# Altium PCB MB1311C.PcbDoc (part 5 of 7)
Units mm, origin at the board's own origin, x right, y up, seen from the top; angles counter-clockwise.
Board outline 100.03 x 67.03 mm, 6 copper layers (Top Layer, layer2, layer3, layer4, layer5, Bottom Layer), stack 1.208 mm thick; 366 components, 356 nets, 1582 pads, 964 vias.
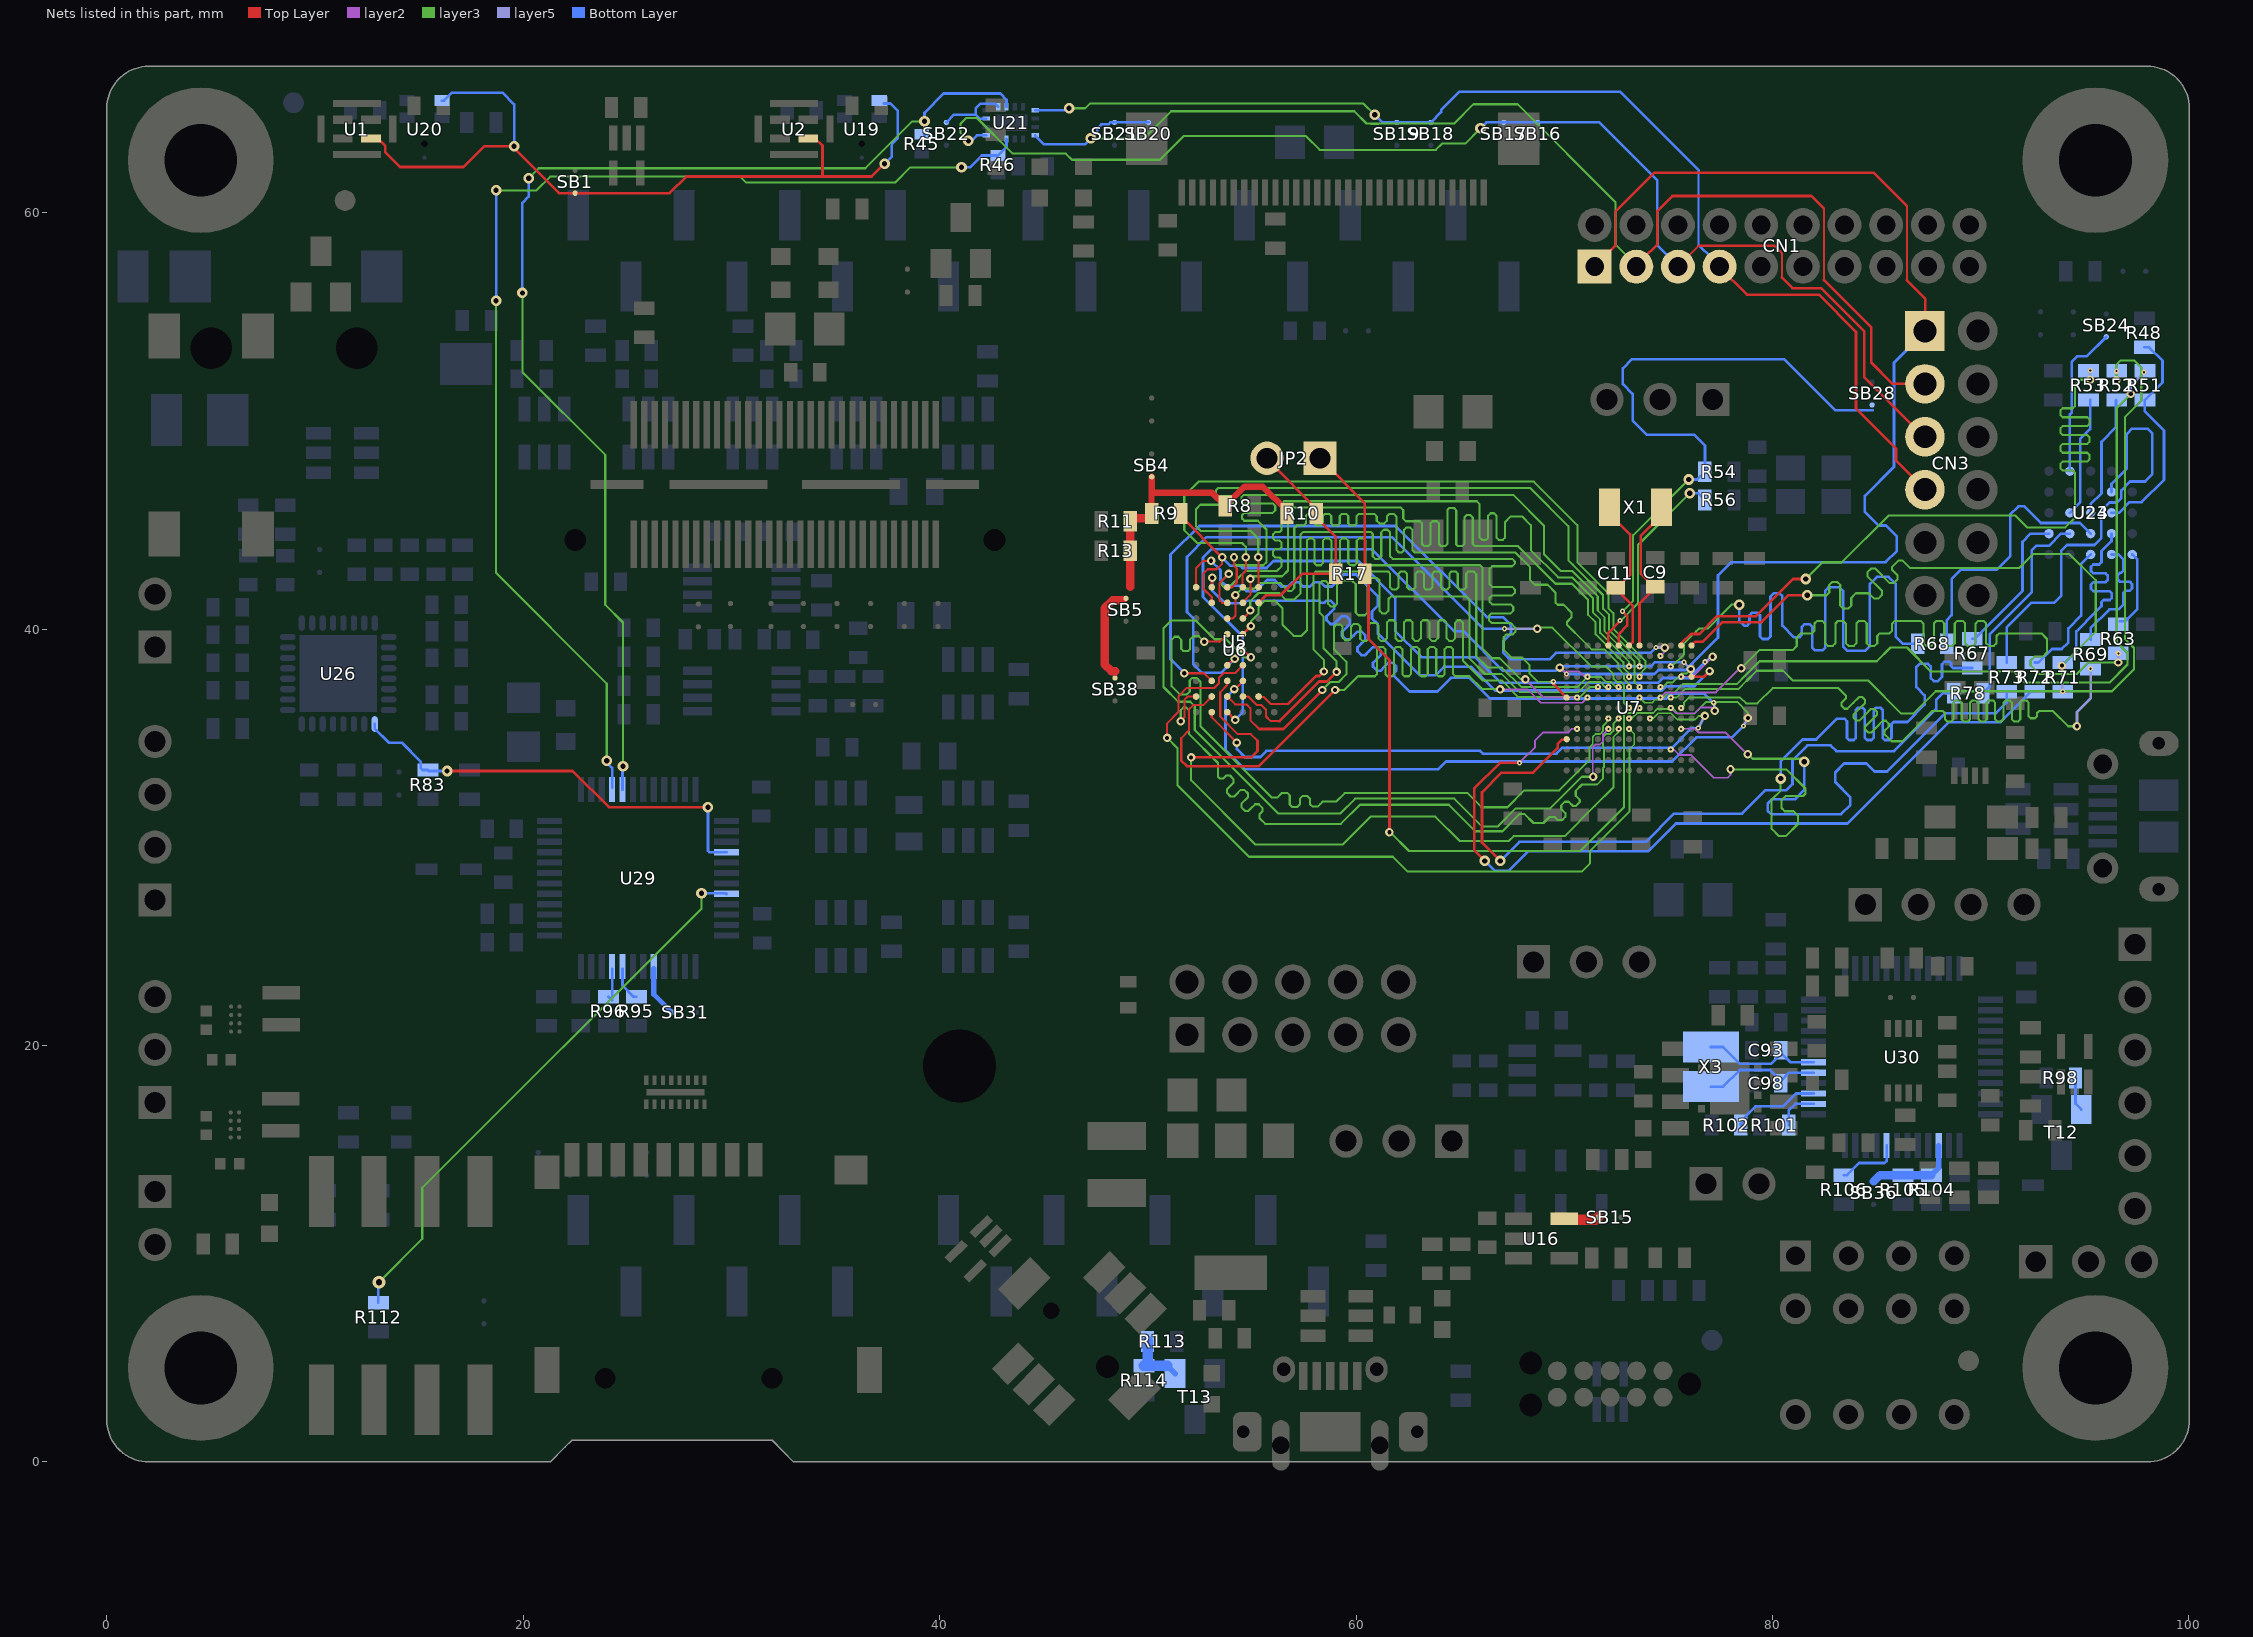
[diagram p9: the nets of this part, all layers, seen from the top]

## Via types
v1: diameter 0.508, hole 0.254, Top Layer to Bottom Layer, tented both sides, 462 vias
v2: diameter 0.61, hole 0.305, Top Layer to Bottom Layer, tented both sides, 126 vias
v3: diameter 0.406, hole 0.203, layer2 to layer5, tented both sides, 109 vias
v4: diameter 0.25, hole 0.1, Top Layer to layer2, tented both sides, 80 vias
v5: diameter 0.25, hole 0.1, Top Layer to layer3, tented both sides, 78 vias
v6: diameter 0.25, hole 0.1, layer5 to Bottom Layer, tented both sides, 52 vias
v7: diameter 0.406, hole 0.203, Top Layer to Bottom Layer, tented both sides, 48 vias
v8: diameter 0.508, hole 0.254, layer2 to layer5, tented both sides, 4 vias
v9: diameter 0.406, hole 0.203, layer2 to layer5, 3 vias
v10: diameter 0.25, hole 0.1, layer5 to Bottom Layer, tented bottom, 1 vias
v11: diameter 0.25, hole 0.1, Top Layer to layer3, tented top, 1 vias

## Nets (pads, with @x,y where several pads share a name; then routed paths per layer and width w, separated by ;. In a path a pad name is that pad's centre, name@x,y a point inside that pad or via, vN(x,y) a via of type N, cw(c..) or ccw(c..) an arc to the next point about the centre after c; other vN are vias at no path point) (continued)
NetR83_2: R83.2 U26.25 U29.28 | length 21
  Top Layer w0.127: v1(16.343,33.183) 22.371,33.183 24.111,31.443 v1(28.873,31.443)
  Bottom Layer w0.127: U26.25@12.863,35.443 12.863,35.233 13.558,34.538 14.168,34.538 15.073,33.633 15.073,33.323 15.167,33.229 R83.2@15.423,33.229 15.469,33.183 v1(16.343,33.183) ; v1(28.873,31.443) 28.873,29.359 28.949,29.283 U29.28@29.771,29.283
NetR95_1: R95.1 U29.44 | length 1.7
  Bottom Layer w0.127: U29.44@24.771,23.683 24.771,22.875 25.307,22.339 R95.1@25.438,22.339
NetR96_1: R96.1 U29.45 | length 1.8
  Bottom Layer w0.127: R96.1@24.096,22.339 24.271,22.164 U29.45@24.271,23.683
NetR98_1: R98.1 T12.2 | length 1.6
  Bottom Layer w0.127: R98.1@94.553,18.443 94.553,17.203 T12.2@94.833,16.923
NetR101_2: R101.2 U30.2 | length 2
  Bottom Layer w0.127: R101.2@80.783,16.173 80.783,16.866 81.11,17.193 U30.2@81.983,17.193
NetR102_2: R102.2 U30.3 | length 4.3
  Bottom Layer w0.127: R102.2@78.463,16.213 R102.2@78.483,16.233 ; R102.2@78.483,16.173 R102.2@78.483,16.233 ; U30.3@81.983,17.693 81.133,17.693 80.526,17.086 79.207,17.086 78.702,16.581 78.702,16.452 R102.2@78.483,16.233
NetR104_1: R104.1 R105.2 SB36.2 U30.39 | length 4.5
  Bottom Layer w0.254: R104.1@87.643,13.773 87.983,14.113 U30.39@87.983,15.193
  Bottom Layer w0.4: SB36.2@84.863,13.463 85.173,13.773 R105.2@86.273,13.773 R104.1@87.643,13.773
NetR106_1: R106.1 U30.44 | length 3.1
  Bottom Layer w0.127: R106.1@83.423,13.773 83.583,13.773 84.163,14.353 85.383,14.353 85.483,14.453 U30.44@85.483,15.193
NetR112_2: R112.2 U29.32 | length 27.3
  layer3 w0.102: v2(13.073,8.633) 15.153,10.713 15.153,13.163 28.563,26.573 v1(28.563,27.313)
  Bottom Layer w0.127: R112.2@13.043,7.643 13.043,8.603 v2(13.073,8.633) ; v1(28.563,27.313) 29.721,27.313 29.761,27.273 U29.32@29.771,27.283
NetR113_2: R113.2 R114.2 T13.1 | length 2.9
  Bottom Layer w0.254: R114.2@49.813,4.613 R114.2@49.988,4.788 ; T13.1@50.938,4.613 T13.1@51.313,4.238
  Bottom Layer w0.5: R114.2@49.813,4.613 T13.1@50.938,4.613 ; R114.2@49.988,4.788 R113.2@49.988,5.788
NetSB1_1: SB1.1 U1.4 U2.4 U19.1 U20.1 | length 39.2
  Top Layer w0.127: U1.4@12.688,63.563 13.023,63.563 13.373,63.213 13.373,62.914 14.094,62.193 17.133,62.193 18.123,63.183 v1(19.563,63.183) 19.563,63.093 21.723,60.933 SB1.1@22.493,60.933 27.033,60.933 27.833,61.733 34.373,61.733 ; U2.4@33.688,63.563 34.023,63.563 34.373,63.213 34.373,61.733 ; v1(37.357,62.351) 36.739,61.733 34.373,61.733
  Bottom Layer w0.127: U20.1@16.101,65.377 16.207,65.377 16.587,65.757 19.008,65.757 19.563,65.203 v1(19.563,63.183) ; U19.1@37.32,65.244 37.635,65.244 37.994,64.885 37.994,63.582 37.709,63.297 37.709,62.703 v1(37.357,62.351)
NetSB15_2: SB15.2 U16.5 | length 1.7
  Top Layer w0.5: U16.5@70,11.676 70.048,11.628 71.518,11.628 SB15.2@71.633,11.743
NetSB22_2: SB22.2 U21.7 U21.9 | length 3.7
  Bottom Layer w0.127: SB22.2@40.323,64.333 40.697,64.707 41.733,64.707 ; U21.7@42.238,64.513 41.927,64.513 41.733,64.707 ; U21.9@42.813,65.088 42.668,65.233 41.972,65.233 41.733,64.994 41.733,64.707
NetSB31_2: SB31.2 U29.41 | length 2.5
  Bottom Layer w0.254: U29.41@26.271,23.683 26.271,22.457 27.135,21.593 SB31.2@27.223,21.593
OCTOSPI_CLK: R73.2 U23.B2 U24.B2 | length 20.5
  Bottom Layer w0.127: R73.2@91.253,38.393 91.253,40.083 92.428,41.259 93.528,41.259 93.867,41.597 93.867,43.755 94.145,44.033 95.471,44.033 95.792,44.354 95.792,45.68 96.188,46.076 96.549,46.076 96.758,46.285 96.758,46.664 97.183,47.089 97.902,47.089 98.25,47.437 98.25,49.386 98.015,49.621 97.281,49.621 97.025,49.365 97.025,47.717 96.283,46.975 U23.B2@96.283,46.583
OCTOSPI_CS: R48.1 R51.2 U23.C2 U24.C2 | length 10.8
  Bottom Layer w0.127: U23.C2@96.283,45.583 96.636,45.583 97.146,46.093 97.734,46.093 98.807,47.166 98.807,49.533 97.888,50.452 R51.2@97.888,51.003 98.733,51.848 98.733,52.888 98.088,53.533 R48.1@97.863,53.533
OCTOSPI_DQS: R52.2 U23.C3 U24.C3 | length 5.9
  Bottom Layer w0.127: U23.C3@95.283,45.583 95.283,45.995 95.803,46.515 95.803,48.993 96.503,49.693 R52.2@96.503,51.003
OCTOSPI_IO0: R68.2 U23.D3 U24.D3 | length 13
  Bottom Layer w0.127: R68.2@88.374,39.297 88.373,39.298 88.373,40.428 88.608,40.663 88.608,42.408 89.055,42.855 90.777,42.855 91.417,43.495 91.417,45.491 91.816,45.89 92.098,45.89 92.895,45.093 94.773,45.093 U23.D3@95.283,44.583
OCTOSPI_IO1: R71.2 U23.D2 U24.D2 | length 10.2
  Bottom Layer w0.127: R71.2@93.943,38.393 94.063,38.393 94.592,38.922 94.592,39.892 95.516,40.815 95.652,40.951 95.803,41.102 95.803,41.287 95.91,41.394 96.196,41.394 96.303,41.5 96.303,41.714 96.196,41.821 95.803,41.821 95.41,41.821 95.303,41.927 95.303,42.141 95.41,42.247 95.803,42.247 95.996,42.247 96.103,42.354 96.103,42.568 95.996,42.674 95.803,42.674 95.41,42.674 95.303,42.781 95.303,42.995 95.41,43.101 95.696,43.101 95.803,43.208 95.803,43.528 95.803,43.742 96.283,44.222 U23.D2@96.283,44.583
OCTOSPI_IO2: R53.2 U23.C4 U24.C4 | length 5.8
  Bottom Layer w0.127: U23.C4@94.283,45.583 94.783,46.083 94.783,49.123 95.263,49.603 R53.2@95.263,51.013
OCTOSPI_IO3: R78.2 U23.D4 U24.D4 | length 10
  Bottom Layer w0.127: R78.2@90.114,36.917 90.433,37.236 90.433,39.741 92.45,41.758 92.45,43.78 92.668,43.998 93.286,43.998 93.871,44.583 U23.D4@94.283,44.583
OCTOSPI_IO4: R67.2 U23.D5 U24.D5 | length 7.2
  Bottom Layer w0.127: R67.2@89.594,39.527 89.699,39.527 92.01,41.838 92.01,44.187 92.406,44.583 U23.D5@93.283,44.583
OCTOSPI_IO5: R72.2 U23.E3 U24.E3 | length 6.7
  Bottom Layer w0.127: R72.2@92.603,38.393 92.779,38.393 93.43,39.044 93.892,39.044 94.209,39.361 94.209,40.025 94.825,40.641 94.825,43.125 U23.E3@95.283,43.583
OCTOSPI_IO6: R69.2 U23.E2 U24.E2 | length 6.4
  Bottom Layer w0.127: R69.2@95.283,39.493 95.283,40.044 96.183,40.944 96.632,40.944 96.857,41.169 96.857,41.644 96.857,41.737 96.964,41.844 97.163,41.844 97.27,41.95 97.27,42.164 97.163,42.27 96.857,42.27 96.697,42.27 96.59,42.377 96.59,42.591 96.697,42.697 96.75,42.697 96.857,42.804 96.857,43.124 96.857,43.338 96.612,43.583 U23.E2@96.283,43.583
OCTOSPI_IO7: R63.2 U23.E1 U24.E1 | length 3.8
  Bottom Layer w0.127: R63.2@96.673,40.373 96.94,40.373 97.524,40.957 97.524,43.342 U23.E1@97.283,43.583
OCTOSPI_RESET: SB24.2 U23.A4 U24.A4 | length 7.4
  Bottom Layer w0.127: U23.A4@94.283,47.583 94.283,50.303 94.383,50.403 94.383,52.843 94.633,53.093 95.093,53.093 SB24.2@96.033,54.033
OCTOSPIM_P2_CLK: R73.1 U7.B9 | length 26.8
  layer2 w0.088: v4(75.617,35.208) 76.27,35.208 76.441,35.037 77.74,35.037 78.788,33.989 v3(78.82,33.989)
  layer3 w0.102: v3(78.82,33.989) v3(78.82,33.989) 79.042,33.768 81.378,33.768 v1(81.523,33.623)
  Bottom Layer w0.127: v1(81.523,33.623) 81.523,32.269 81.073,31.819 79.965,31.819 79.775,31.629 79.775,31.266 79.935,31.106 83.296,31.106 83.746,31.556 83.746,31.916 83.017,32.645 83.017,33.112 83.446,33.541 84.517,33.541 84.903,33.155 85.512,33.155 88.314,35.957 90.746,35.957 91.253,36.464 R73.1@91.253,36.993
OCTOSPIM_P2_CS: R51.1 U7.F6 | length 40.5
  layer3 w0.088: v5(73.617,36.708) 73.865,36.46 74.213,36.46 74.219,36.461 74.36,36.602 74.658,36.602 75.013,36.958 75.312,36.958 75.705,37.351
  layer3 w0.102: 75.705,37.351 78.281,37.351 78.524,37.594 78.524,37.598 79.378,38.452 85.01,38.452 85.668,39.11 86.465,39.11 87.619,37.956 91.598,37.956 92.126,37.428 96.187,37.428 97.053,38.294 97.053,38.848 96.763,39.138 96.538,39.363 96.538,50.613 v3(97.213,51.288)
  layer5 w0.127: v3(97.213,51.288) 97.213,51.693 v6(97.853,52.333)
OCTOSPIM_P2_DQS: R52.1 U7.C6 | length 42.2
  layer3 w0.088: v5(75.117,36.708) 75.392,36.708 75.807,37.122 78.372,37.122 78.753,37.503
  layer3 w0.102: 78.753,37.503 79.245,37.995 80.514,37.995 80.978,37.531 84.599,37.531 86.192,35.938 86.764,35.938 87.837,37.011 96.311,37.011 97.363,38.063 97.363,39.088 96.938,39.513 96.938,50.188 97.663,50.913 97.713,50.963 97.713,52.563 97.388,52.888 96.713,52.888 96.513,52.688 v3@96.513,51.963 ; v3@96.563,51.888 v3@96.563,51.963
  layer5 w0.127: v3(96.523,51.943) v6(96.523,52.383)
OCTOSPIM_P2_IO0: R68.1 U7.C3 | length 32.9
  layer3 w0.088: v5(75.117,38.208) 75.17,38.208 75.76,38.798 75.76,39.308 76.343,39.891
  layer3 w0.102: 76.343,39.891 76.47,40.018 76.878,40.018 78.033,41.173 v1(78.403,41.173)
  Bottom Layer w0.127: v1(78.403,41.173) 78.403,40.4 78.65,40.153 78.775,40.153 78.901,40.278 78.901,40.657 79.026,40.782 79.277,40.782 79.402,40.657 79.402,39.649 79.528,39.524 79.779,39.524 79.904,39.649 79.904,41.555 80.062,41.713 80.339,41.713 80.474,41.578 80.474,40.168 81.039,39.603 81.288,39.603 81.414,39.728 81.414,40.107 81.539,40.232 81.79,40.232 81.915,40.107 81.915,39.099 82.041,38.974 82.399,38.974 82.541,39.116 82.541,41.845 82.695,41.999 83.23,41.999 83.395,41.834 83.395,39.17 83.613,38.952 84.442,38.952 84.678,39.188 84.678,42.16 85.026,42.508 85.576,42.508 85.928,42.156 85.928,39.622 86.253,39.297 R68.1@86.974,39.297
OCTOSPIM_P2_IO1: R71.1 U7.A1 | length 33.3
  Top Layer w0.127: U7.A1@76.117,39.208 76.292,39.383 76.65,39.383 77.6,40.333 79.483,40.333 80.773,41.623 v1(81.673,41.623)
  layer3 w0.102: v1(81.673,41.623) 82.599,41.623 82.731,41.755 82.731,42.12 82.862,42.252 83.126,42.252 83.257,42.12 83.257,41.126 83.389,40.994 83.653,40.994 83.784,41.126 83.784,41.491 84.009,41.716 84.633,41.716 84.892,41.458 85.078,41.458 85.265,41.644 85.265,41.83 84.561,42.534 84.561,42.72 84.748,42.906 84.934,42.906 85.637,42.203 85.824,42.203 86.01,42.389 86.01,42.576 85.751,42.834 85.751,42.985 86.066,43.3 86.237,43.3 86.612,42.925 91.844,42.925 92.517,43.598 94.27,43.598 95.526,42.342 95.526,39.866 v3(93.903,38.243)
  layer5 w0.127: v3(93.903,38.243) 93.921,38.225 93.921,37.015 v6(93.943,36.993)
OCTOSPIM_P2_IO2: R53.1 U7.B1 | length 38.4
  Top Layer w0.127: U7.B1@75.617,39.208 75.617,39.295 76.086,39.764 76.492,39.764 77.347,40.618 79.214,40.618 80.998,42.403 v1(81.603,42.403)
  layer3 w0.102: v1(81.603,42.403) 82.406,43.206 83.335,43.206 85.579,45.45 91.656,45.45 92.225,44.881 94.064,44.881 94.532,45.349 94.532,47.506 94.425,47.613 93.939,47.613 93.832,47.719 93.832,47.933 93.939,48.04 95.125,48.04 95.232,48.146 95.232,48.36 95.125,48.467 93.939,48.467 93.832,48.573 93.832,48.787 93.939,48.894 95.125,48.894 95.232,49 95.232,49.214 95.125,49.321 93.939,49.321 93.832,49.427 93.832,49.641 93.939,49.748 95.125,49.748 95.232,49.854 95.232,50.068 95.125,50.175 93.939,50.175 93.832,50.281 93.832,50.495 93.939,50.602 94.425,50.602 94.532,50.708 94.532,51.696 94.809,51.973 v3(95.263,51.973)
  layer5 w0.127: v3(95.263,51.973) v6(95.263,52.413)
OCTOSPIM_P2_IO3: R78.1 U7.N10 | length 35.2
  Top Layer w0.127: v1(66.933,28.861) 66.053,29.741 66.053,32.158 66.997,33.102 68.498,33.102 69.681,34.285 69.681,34.473 69.892,34.684 70.116,34.684 U7.N10@70.117,34.708
  Bottom Layer w0.127: v1(66.933,28.861) 67.85,29.778 73.924,29.778 75.279,31.133 78.545,31.133 79.67,32.258 80.667,32.258 80.961,32.552 80.961,33.69 81.684,34.413 82.793,34.413 83.075,34.131 85.837,34.131 87.861,36.155 87.861,36.589 88.189,36.917 R78.1@88.714,36.917
OCTOSPIM_P2_IO4: R67.1 U7.C11 | length 37.8
  layer2 w0.088: v4(75.117,34.208) 75.264,34.208 75.367,34.105 75.514,33.959 75.515,33.958 75.72,33.958 76.084,33.957 77.18,32.861 77.854,32.861 77.986,32.993 v3(77.986,33.26)
  layer3 w0.102: v3(77.986,33.26) 80.669,33.26 81.588,32.341 81.588,32.1 81.47,31.982 80.636,31.982 80.438,31.784 80.438,31.407 80.594,31.251 81.02,31.251 81.226,31.045 81.226,30.639 80.641,30.054 80.318,30.054 79.962,30.41 79.962,31.81 80.393,32.241 v1(80.393,32.819)
  Bottom Layer w0.127: v1(80.393,32.819) 80.393,33.637 81.452,34.696 82.102,34.696 83.098,35.692 83.454,35.692 83.582,35.564 83.582,34.774 83.689,34.667 83.903,34.667 84.009,34.774 84.009,36.112 84.116,36.219 84.33,36.219 84.436,36.112 84.436,34.774 84.543,34.667 84.757,34.667 84.863,34.774 84.863,36.112 84.97,36.219 85.184,36.219 85.29,36.112 85.29,34.774 85.397,34.667 85.611,34.667 85.717,34.774 85.717,35.429 85.824,35.536 86.478,35.536 87.313,36.371 87.313,36.813 86.913,37.213 86.913,38.175 87.069,38.331 87.469,38.331 87.601,38.199 87.601,37.652 87.757,37.496 87.944,37.496 88.142,37.694 88.142,38.305 88.27,38.433 88.5,38.433 88.575,38.358 88.575,38.235 88.683,38.127 R67.1@89.594,38.127
OCTOSPIM_P2_IO5: R72.1 U7.M9 | length 40.2
  Top Layer w0.127: v1(66.189,28.861) 65.673,29.377 65.673,32.337 66.909,33.573 v4(67.848,33.573)
  layer2 w0.088: v4(67.848,33.573) 68.601,34.326 68.601,34.656 68.983,35.038 70.198,35.038 70.368,35.208 v4(70.617,35.208)
  Bottom Layer w0.127: v1(66.189,28.861) 66.664,28.386 67.32,28.386 68.257,29.323 74.025,29.323 75.359,30.657 83.607,30.657 86.248,33.298 88.481,35.531 90.964,35.531 92.426,36.993 R72.1@92.603,36.993
OCTOSPIM_P2_IO6: R69.1 U7.B7 | length 39.2
  layer3 w0.088: v5(75.617,36.208) 75.756,36.347 75.756,36.485 75.977,36.706 78.458,36.706 78.736,36.428 79.278,36.428
  layer3 w0.102: 79.278,36.428 80.012,37.162 83.173,37.162 83.315,37.02 83.528,36.807 83.528,36.665 83.317,36.453 83.317,36.311 83.459,36.169 83.601,36.169 83.884,36.451 84.166,36.734 84.308,36.734 84.45,36.592 84.45,36.45 84.168,36.167 83.885,35.885 83.885,35.742 84.028,35.6 84.17,35.6 84.452,35.883 84.735,36.165 84.877,36.165 85.019,36.023 85.019,35.881 84.736,35.599 84.454,35.316 84.454,35.174 84.596,35.032 84.738,35.032 85.021,35.314 85.303,35.597 85.445,35.597 85.587,35.455 85.587,35.313 85.376,35.101 85.376,34.959 85.589,34.746 85.724,34.611 86.228,34.611 87.683,36.066 87.884,36.066 88.185,36.066 88.286,35.965 88.286,35.666 88.386,35.566 88.587,35.566 88.688,35.666 88.688,36.066 88.688,36.465 88.788,36.566 88.989,36.566 89.09,36.465 89.09,36.066 89.09,35.666 89.19,35.566 89.391,35.566 89.492,35.666 89.492,36.066 89.492,36.465 89.592,36.566 89.793,36.566 89.894,36.465 89.894,36.066 89.894,35.666 89.994,35.566 90.195,35.566 90.296,35.666 90.296,36.066 90.296,36.465 90.396,36.566 90.597,36.566 90.698,36.465 90.698,36.066 90.698,35.666 90.798,35.566 90.999,35.566 91.1,35.666 91.1,36.066 91.1,36.465 91.2,36.566 91.401,36.566 91.502,36.465 91.502,36.066 91.502,35.666 91.602,35.566 91.803,35.566 91.904,35.666 91.904,36.066 91.904,36.465 92.004,36.566 92.205,36.566 92.306,36.465 92.306,36.066 92.306,35.813 92.406,35.712 92.607,35.712 92.708,35.813 92.708,35.965 92.808,36.066 92.954,36.066 93.466,36.066 94.202,35.33 v3(94.626,35.33)
  layer5 w0.127: v3(94.626,35.33) 94.626,36.016 95.283,36.673 v6(95.283,38.093)
OCTOSPIM_P2_IO7: R63.1 U7.D6 | length 42.1
  layer2 w0.088: v4(74.617,36.708) 74.866,36.958 77.283,36.958 78.438,38.113 v3(78.499,38.113)
  layer3 w0.088: v3(78.499,38.113) 78.508,38.113 78.889,38.494
  layer3 w0.102: v3(78.499,38.113) 79.375,38.989 80.971,38.989 81.168,39.187 81.17,39.188 81.17,39.593 81.367,39.79 81.772,39.79 81.897,39.79 82.023,39.915 82.023,40.264 82.148,40.39 82.399,40.39 82.525,40.264 82.525,39.79 82.525,39.316 82.65,39.19 82.901,39.19 83.027,39.316 83.027,39.79 83.027,40.264 83.152,40.39 83.403,40.39 83.529,40.264 83.529,39.79 83.529,39.316 83.654,39.19 83.905,39.19 84.031,39.316 84.031,39.79 84.031,40.264 84.156,40.39 84.407,40.39 84.533,40.264 84.533,39.79 84.533,39.316 84.658,39.19 84.909,39.19 85.035,39.316 85.035,39.665 85.16,39.79 85.496,39.79 85.621,39.79 85.747,39.915 85.747,40.265 85.872,40.39 86.123,40.39 86.875,40.39 87.126,40.39 87.252,40.265 87.252,39.79 87.252,39.315 87.377,39.19 87.628,39.19 87.753,39.315 87.753,39.79 87.753,40.265 87.879,40.39 88.129,40.39 88.255,40.265 88.255,39.79 88.255,39.315 88.38,39.19 88.631,39.19 88.756,39.315 88.756,39.79 88.756,40.265 88.882,40.39 89.133,40.39 89.258,40.265 89.258,39.79 89.258,39.315 89.383,39.19 89.634,39.19 89.76,39.315 89.76,39.79 89.76,40.265 89.885,40.39 90.136,40.39 90.261,40.265 90.261,39.79 90.261,39.315 90.387,39.19 90.637,39.19 90.763,39.315 90.763,39.665 90.888,39.79 91.007,39.79 92.922,39.79 93.189,39.523 93.189,38.884 92.982,38.677 92.594,38.677 92.404,38.487 92.404,38.255 92.816,37.843 94.611,37.843 95.161,38.393 v3(96.613,38.393)
  layer5 w0.127: v3(96.613,38.393) v6(96.613,38.833)
OSC32_IN: C9.2 U7.F1 X1.1 | length 8
  Top Layer w0.127: U7.F1@73.617,39.208 73.617,41.229 74.361,41.974 73.673,42.662 73.673,44.473 74.521,45.321 X1.1@74.521,46.241
OSC32_OUT: C11.2 U7.G1 X1.2 | length 8.1
  Top Layer w0.127: X1.2@72.221,46.241 72.221,45.485 73.165,44.541 73.165,42.606 72.482,41.923 73.283,41.122 73.283,39.374 U7.G1@73.117,39.208
OSC_IN: C98.2 U30.5 X3.2 | length 5.7
  Bottom Layer w0.127: X3.2@77.043,18.023 77.633,18.023 78.433,18.823 79.873,18.823 80.403,18.293 80.803,18.693 U30.5@81.983,18.693
OSC_IN_PH0: R54.2 SB28.1 U7.H1 | length 31.7
  Top Layer w0.12: U7.H1@72.617,39.208 72.623,39.214 72.623,39.763 73.023,40.163 73.023,40.623 v5(72.793,40.853)
  layer3 w0.102: v5(72.793,40.853) 72.803,40.853 73.311,41.361 73.311,44.511 v1(75.983,47.183)
  Bottom Layer w0.127: v1(75.983,47.183) 76.383,47.183 R54.2@76.753,47.553 ; R54.2@76.763,47.513 76.763,48.813 76.238,49.338 73.963,49.338 73.288,50.013 73.288,51.288 72.813,51.763 72.813,52.513 73.263,52.963 80.563,52.963 83.013,50.513 84.813,50.513
OSC_OUT: C93.2 U30.6 X3.1 | length 5.7
  Bottom Layer w0.127: X3.1@77.043,19.923 77.633,19.923 78.443,19.113 79.933,19.113 80.443,19.623 80.873,19.193 U30.6@81.983,19.193
OSC_OUT_PH1: R56.2 U7.J1 | length 9.8
  Top Layer w0.127: U7.J1@72.117,39.208 72.117,39.817 72.68,40.38 v5(72.68,40.406)
  layer3 w0.102: v5(72.68,40.406) 72.708,40.406 73.543,41.241 73.543,44.033 v1(76.033,46.523)
  Bottom Layer w0.127: v1(76.033,46.523) 76.433,46.523 R56.2@76.753,46.203
PMOD#1: CN1.1 CN3.1 U7.L4 | length 59.7
  Top Layer w0.102: 72.47,58.422 72.47,60.051 ; 86.456,56.746 86.456,60.31
  Top Layer w0.127: CN1.1@71.463,57.813 71.861,57.813 72.47,58.422 ; 72.47,60.051 74.339,61.92 84.846,61.92 86.456,60.31 ; 86.456,56.746 87.333,55.869 87.333,54.883 CN3.1@87.513,54.703
  layer2 w0.088: v3(69.788,38.148) 69.977,37.959 70.725,37.959 70.976,37.708 v4(71.117,37.708)
  layer5 w0.127: v3(69.788,38.148) 70.098,37.838 v6(70.109,37.838)
  Bottom Layer w0.127: v6(70.109,37.838) 74.326,37.838 74.522,38.034 75.835,38.034 77.389,39.588 77.389,42.576 78.025,43.212 85.439,43.212 85.975,43.748 85.975,44.443 85.446,44.972 85.093,44.972 84.439,45.626 84.439,46.392 85.841,47.794 85.841,52.789 87.513,54.461 CN3.1@87.513,54.603 ; CN1.1@71.123,57.813 CN1.1@71.463,57.813
PMOD#2: CN1.2 CN3.2 SB20.2 SB21.2 U21.16 | length 61.1
  Top Layer w0.102: 74.47,58.466 74.47,60.077 ; 82.47,56.765 82.47,60.2
  Top Layer w0.127: CN1.2@73.463,57.813 73.817,57.813 74.47,58.466 ; 74.47,60.077 75.194,60.801 81.869,60.801 82.47,60.2 ; 82.47,56.765 84.738,54.497 84.738,52.813 85.778,51.773 CN3.2@87.326,51.773 ; CN3.2@86.993,52.163 CN3.2@87.513,52.163
  layer3 w0.102: v1(47.263,63.563) 49.813,63.563 51.119,64.869 59.919,64.869 60.506,64.282 60.703,64.282 60.714,64.271 61.072,64.271 61.083,64.282 64.713,64.282 65.634,65.203 67.764,65.203 72.456,60.511 72.456,58.484 73.127,57.813 CN1.2@73.463,57.813
  Bottom Layer w0.127: U21.16@44.588,63.713 45.023,63.278 46.978,63.278 v1(47.263,63.563) 47.575,63.875 47.575,64.04 47.776,64.241 48.112,64.241 48.204,64.333 SB21.2@48.403,64.333 SB20.2@50.033,64.333
PMOD#3: CN1.3 CN3.3 SB16.2 SB17.2 U21.5 | length 61.3
  Top Layer w0.102: CN1.3@75.463,57.407 76.462,58.406 80.102,58.406 80.456,58.052 80.456,56.879
  Top Layer w0.127: 80.456,56.879 80.963,56.372 82.338,56.372 84.413,54.297 84.413,52.089 86.879,49.623 CN3.3@87.513,49.623
  layer3 w0.102: v1(41.383,63.443) 41.011,63.815 41.011,64.281 41.275,64.545 41.799,64.545 43.511,62.833 46.063,62.833 46.358,62.538 50.588,62.538 51.731,63.681 57.592,63.681 58.258,63.015 63.828,63.015 64.127,63.314 65.241,63.314 v1(65.98,64.053)
  Bottom Layer w0.102: 74.47,58.422 74.47,61.546
  Bottom Layer w0.127: v1(41.383,63.443) 41.522,63.443 41.792,63.713 U21.5@42.238,63.713 ; v1(65.98,64.053) 66.26,64.333 SB17.2@67.093,64.333 SB16.2@68.733,64.333 71.683,64.333 74.47,61.546 ; 74.47,58.422 75.079,57.813 CN1.3@75.463,57.813
PMOD#4: CN1.4 CN3.4 SB18.2 SB19.2 U21.13 | length 56.7
  Top Layer w0.127: CN1.4@77.463,57.813 CN1.4@77.463,57.407 77.463,57.364 78.77,56.057 82.229,56.057 84.013,54.273 84.013,50.583 85.934,48.662 85.934,48.085 CN3.4@87.326,46.693
  layer3 w0.102: v1(46.217,65.01) 46.992,65.01 47.218,65.236 60.36,65.236 v1(60.893,64.703)
  Bottom Layer w0.102: 76.456,58.456 76.456,62.042
  Bottom Layer w0.127: U21.13@44.588,64.913 46.12,64.913 v1(46.217,65.01) ; v1(60.893,64.703) 61.263,64.333 SB19.2@61.963,64.333 SB18.2@63.593,64.333 64.093,64.833 64.093,64.933 64.973,65.813 72.685,65.813 76.456,62.042 ; 76.456,58.456 77.099,57.813 CN1.4@77.463,57.813
PMOD_SEL_0: R46.1 U21.3 U29.16 | length 57
  layer3 w0.102: v1(18.698,55.768) 18.698,42.688 24.013,37.373 v1(24.013,33.673) ; v1(18.698,61.068) 20.64,61.068 21.301,61.729 30.422,61.729 30.711,61.44 37.856,61.44 38.589,62.173 v1(41.053,62.173)
  Bottom Layer w0.127: v1(18.698,55.768) v1(18.698,61.068) ; v1(24.013,33.673) 24.013,33.583 24.271,33.325 U29.16@24.271,32.383 ; v1(41.053,62.173) 41.462,62.173 42.032,62.743 R46.1@42.803,62.743 43.213,63.153 U21.3@43.213,63.538
PMOD_SEL_1: R45.2 U21.10 U29.17 | length 57.5
  layer3 w0.102: v1(19.963,56.143) 19.963,52.345 23.944,48.364 23.944,41.162 24.793,40.313 v1(24.793,33.403) ; v1(20.263,61.653) 20.741,62.131 36.429,62.131 38.682,64.384 v1(39.274,64.384)
  Bottom Layer w0.127: v1(19.963,56.143) 19.963,60.463 20.263,60.763 v1(20.263,61.653) ; U29.17@24.771,32.283 24.771,33.381 v1(24.793,33.403) ; R45.2@39.274,63.719 v1(39.274,64.384) 39.274,64.794 40.198,65.718 42.914,65.718 43.213,65.419 U21.10@43.213,65.088
PSRAM_A0: U5.A3 U6.A3 U7.F5 | length 35.9
  Top Layer w0.102: U5.A3@53.819,42.008 54.046,42.008 54.272,42.234 54.272,42.909 54.14,43.041 v7(54.14,43.444)
  layer3 w0.088: 71.612,40.89 71.934,40.568 71.934,39.89 73.368,38.456 73.368,37.457 v5(73.617,37.208)
  layer3 w0.102: v7(54.14,43.444) 54.14,43.159 54.234,43.065 55.553,43.065 55.703,43.215 55.703,44.783 55.286,45.2 54.633,45.2 54.521,45.311 54.521,45.469 54.633,45.581 55.995,45.581 56.122,45.708 56.122,45.911 55.995,46.038 54.615,46.038 54.496,46.157 54.496,46.325 54.615,46.444 66.178,46.444 67.549,46.444 69.02,44.973 69.02,44.256 69.02,43.603 69.836,42.787 70.392,42.787 71.612,41.567 71.612,40.89
PSRAM_A1: U5.A4 U6.A4 U7.F4 | length 35.7
  Top Layer w0.102: U5.A4@54.569,42.008 54.547,42.03 54.547,42.628 54.709,42.79 v7(54.709,43.444)
  layer3 w0.088: 72.121,41.008 72.361,40.768 72.361,40.018 73.902,38.478 73.902,38.113 73.617,37.828 v5(73.617,37.708)
  layer3 w0.102: v7(54.709,43.444) 54.709,43.951 54.527,44.133 52.367,44.133 51.749,44.751 51.749,46.391 52.437,47.079 68.537,47.079 70.632,44.984 70.632,43.214 72.121,41.725 72.121,41.008
PSRAM_A2: U5.A5 U6.A5 U7.F3 | length 35.6
  Top Layer w0.102: U5.A5@55.319,42.008 v7@55.319,43.447
  layer3 w0.088: 71.864,40.977 72.158,40.683 72.158,39.944 73.617,38.484 v5(73.617,38.208)
  layer3 w0.102: v7(55.305,43.444) 55.305,44.35 54.946,44.709 52.542,44.709 52.318,44.933 52.318,45.763 52.523,45.968 54.028,45.968 54.122,46.062 54.122,46.296 54.043,46.375 53.378,46.375 53.277,46.476 53.277,46.673 53.378,46.774 66.28,46.774 68.367,46.774 70.199,44.942 70.199,43.299 70.407,43.091 71.864,41.634 71.864,40.977
PSRAM_A3: U5.B3 U6.B3 U7.G3 | length 36.3
  Top Layer w0.102: U5.B3@53.819,41.258 53.569,41.258 53.441,41.386 53.441,41.704 53.441,42.199 v7(53.891,42.649)
  layer3 w0.088: 71.39,40.789 71.721,40.458 71.721,39.813 72.85,38.684 73.117,38.417 v5(73.117,38.208)
  layer3 w0.102: v7(53.891,42.649) 53.534,42.292 53.534,42.139 53.705,41.968 53.86,41.968 54.679,42.787 56.198,42.787 56.426,43.015 56.426,43.331 56.325,43.433 56.122,43.433 56.02,43.534 56.02,43.737 56.122,43.839 56.325,43.839 56.426,43.941 56.426,44.144 56.325,44.245 56.122,44.245 56.02,44.347 56.02,44.55 56.122,44.652 56.325,44.652 56.426,44.753 56.426,46.012 56.553,46.139 65.799,46.139 65.926,46.012 65.926,44.412 66.053,44.285 66.242,44.285 66.344,44.387 66.344,45.441 66.463,45.561 66.631,45.561 66.75,45.441 66.75,44.387 66.852,44.285 67.055,44.285 67.156,44.387 67.156,45.135 67.434,45.413 67.971,45.413 68.401,44.983 68.401,43.791 69.71,42.482 70.373,42.482 71.39,41.465 71.39,40.789
PSRAM_A4: U5.B4 U6.B4 U7.G4 | length 36.1
  Top Layer w0.102: U5.B4@54.569,41.258 54.569,41.284 54.928,41.644 v7(54.928,42.406)
  layer3 w0.088: 71.141,40.684 71.51,40.315 71.51,39.741 72.841,38.41 72.841,38.131 73.117,37.855 v5(73.117,37.708)
  layer3 w0.102: v7(54.928,42.406) 55.055,42.533 56.453,42.533 56.731,42.811 56.731,45.708 56.858,45.835 62.141,45.835 62.268,45.708 62.268,45.301 62.395,45.174 63.069,45.174 63.17,45.073 63.17,44.082 63.272,43.98 63.475,43.98 63.577,44.082 63.577,45.073 63.678,45.174 63.882,45.174 63.983,45.073 63.983,44.082 64.085,43.98 64.288,43.98 64.39,44.082 64.39,45.36 64.39,45.718 64.482,45.81 64.706,45.81 64.816,45.7 64.816,45.38 64.816,44.062 64.898,43.98 65.101,43.98 65.202,44.082 65.202,45.36 65.321,45.479 65.49,45.479 65.609,45.36 65.609,44.082 65.71,43.98 67.78,43.98 69.583,42.177 70.374,42.177 71.141,41.41 71.141,40.684
PSRAM_A5: U5.C3 U6.C3 U7.G5 | length 35.6
  Top Layer w0.102: U5.C3@53.819,40.508 54.086,40.508 54.209,40.631 v7(54.209,41.632)
  layer3 w0.088: 70.523,39.81 71.31,39.023 71.929,39.023 72.595,38.357 72.595,38.113 72.867,37.841 72.867,37.605 73.117,37.355 v5(73.117,37.208)
  layer3 w0.102: v7(54.209,41.632) 54.51,41.933 55.096,41.933 55.382,42.219 56.358,42.219 56.756,41.821 56.888,41.821 57.036,41.969 57.036,44.844 57.163,44.971 57.491,44.971 57.593,45.073 57.593,45.428 57.695,45.53 57.898,45.53 57.999,45.428 57.999,45.073 58.101,44.971 58.304,44.971 58.406,45.073 58.406,45.428 58.507,45.53 58.711,45.53 58.812,45.428 58.812,45.073 58.914,44.971 59.117,44.971 59.219,45.073 59.219,45.428 59.32,45.53 59.523,45.53 59.625,45.428 59.625,45.073 59.727,44.971 59.93,44.971 60.031,45.073 60.031,45.428 60.133,45.53 60.871,45.53 60.998,45.403 60.998,45.2 61.125,45.073 61.354,45.073 61.481,45.2 61.481,45.403 61.608,45.53 61.811,45.53 61.938,45.403 61.938,43.803 62.065,43.676 62.203,43.676 62.304,43.777 62.304,44.768 62.406,44.869 62.609,44.869 62.711,44.768 62.711,43.777 62.812,43.676 67.653,43.676 68.361,42.968 68.361,42.351 68.588,42.124 69.205,42.124 69.584,41.745 69.584,41.264 69.681,41.167 69.969,41.167 70.348,40.789 70.348,40.558 70.131,40.341 70.131,40.202 70.523,39.81
PSRAM_A6: U5.C4 U6.C4 U7.N6 | length 35.9
  Top Layer w0.102: U5.C4@54.569,40.508 54.923,40.862 v7(54.923,40.893)
  Top Layer w0.127: v5(69.476,37.472) 69.476,37.349 U7.N6@70.117,36.708
  layer3 w0.088: 68.088,38.518 68.339,38.267 68.339,37.859 68.726,37.472 v5(69.476,37.472)
  layer3 w0.102: v7(54.923,40.893) 54.923,41.338 55.313,41.728 56.305,41.728 56.608,41.425 57.045,41.425 57.341,41.721 57.341,44.539 57.468,44.666 60.703,44.666 60.805,44.565 60.805,43.49 60.924,43.371 61.092,43.371 61.211,43.49 61.211,44.644 61.335,44.768 61.51,44.768 61.633,44.644 61.633,43.498 61.76,43.371 67.501,43.371 67.628,43.244 67.628,43.142 67.501,43.015 66.536,43.015 66.409,42.888 66.409,42.152 66.536,42.025 67.501,42.025 67.628,41.898 67.628,41.745 67.501,41.618 66.536,41.618 66.409,41.491 66.409,41.313 66.536,41.186 67.425,41.186 67.552,41.059 67.552,40.882 67.425,40.755 66.51,40.755 66.383,40.628 66.383,40.424 66.51,40.297 67.425,40.297 67.653,40.069 67.653,39.866 67.526,39.739 67.221,39.739 67.094,39.612 67.094,39.002 67.475,38.621 67.99,38.621 68.088,38.523 68.088,38.518
PSRAM_A7: U5.D4 U6.D4 U7.M6 | length 35.7
  Top Layer w0.102: U5.D4@54.569,39.758 v7(54.953,40.142)
  layer2 w0.088: v3(68.136,37.58) 69.007,36.708 v4(70.617,36.708)
  layer3 w0.088: 66.9,38.596 67.888,37.608 68.108,37.608 v3(68.136,37.58)
  layer3 w0.102: v7(54.953,40.142) 54.953,40.379 55.309,40.734 55.309,41.037 55.624,41.352 56.11,41.352 56.466,40.996 56.466,40.724 56.466,40.212 57.007,39.671 57.378,39.671 57.646,39.939 57.646,41.263 57.646,44.257 57.75,44.361 57.899,44.361 58.003,44.257 58.003,43.168 58.105,43.066 58.308,43.066 58.41,43.168 58.41,44.242 58.529,44.361 58.697,44.361 58.816,44.242 58.816,43.168 58.918,43.066 59.121,43.066 59.222,43.168 59.222,44.242 59.342,44.361 59.51,44.361 59.629,44.242 59.629,43.168 59.73,43.066 59.934,43.066 60.035,43.168 60.035,44.242 60.154,44.361 60.323,44.361 60.442,44.242 60.442,43.168 60.543,43.066 65.951,43.066 66.078,42.939 66.078,39.056 66.539,38.596 66.9,38.596
PSRAM_A8: U5.H2 U6.H2 U7.L6 | length 38.8
  Top Layer w0.102: 51.6,34.755 51.981,35.136 51.981,36.148 52.179,36.346 52.657,36.346 U5.H2@53.069,36.758
  Top Layer w0.127: 51.6,34.755 51.6,33.684 51.871,33.413 55.333,33.413 v7(58.992,37.072)
  layer2 w0.088: v3(66.917,37.097) 68.242,37.097 68.88,36.459 70.867,36.459 v4(71.117,36.708)
  layer3 w0.102: v7(58.992,37.072) 59.432,37.072 60.093,37.732 60.702,37.732 60.905,37.732 61.007,37.834 61.007,39.027 61.109,39.129 61.312,39.129 61.413,39.027 61.413,37.834 61.515,37.732 61.718,37.732 61.82,37.834 61.82,39.027 61.921,39.129 62.125,39.129 62.226,39.027 62.226,37.834 62.328,37.732 62.531,37.732 62.633,37.834 62.633,39.027 62.734,39.129 62.937,39.129 63.039,39.027 63.039,37.834 63.141,37.732 63.344,37.732 63.445,37.834 63.445,39.027 63.547,39.129 63.75,39.129 63.852,39.027 63.852,37.834 63.953,37.732 64.157,37.732 64.258,37.834 64.258,39.027 64.36,39.129 64.563,39.129 64.665,39.027 64.665,37.834 64.766,37.732 65.443,37.732 66.056,37.12 66.487,37.12 66.894,37.12 v3(66.917,37.097)
PSRAM_A9: U5.H3 U6.H3 U7.K5 | length 37
  Top Layer w0.102: U5.H3@53.819,36.758 54.194,36.383 54.738,36.383 54.926,36.195 54.926,35.625 55.351,35.2
  Top Layer w0.127: 55.351,35.2 56.511,35.2 v7(58.382,37.072)
  layer3 w0.088: 66.994,37.535 67.795,36.734 70.752,36.734 71.226,37.208 v5(71.617,37.208)
  layer3 w0.102: v7(58.382,37.072) 58.763,37.453 59.17,37.453 59.538,37.821 59.538,38.43 58.941,39.027 58.941,40.099 59.063,40.221 59.236,40.221 59.359,40.099 59.359,39.578 59.478,39.459 59.646,39.459 59.765,39.578 59.765,40.12 59.892,40.247 60.074,40.247 60.201,40.12 60.201,39.535 60.302,39.434 60.505,39.434 60.607,39.535 60.607,40.196 60.709,40.297 60.948,40.297 61.075,40.17 61.075,39.555 61.196,39.434 61.368,39.434 61.49,39.555 61.49,40.323 61.592,40.424 61.795,40.424 61.897,40.323 61.897,39.553 62.016,39.434 62.184,39.434 62.303,39.553 62.303,40.323 62.405,40.424 62.608,40.424 62.709,40.323 62.709,39.553 62.828,39.434 62.997,39.434 63.116,39.553 63.116,40.323 63.217,40.424 63.421,40.424 63.522,40.323 63.522,39.553 63.641,39.434 63.809,39.434 63.929,39.553 63.929,40.323 64.03,40.424 64.224,40.424 64.351,40.297 64.351,39.553 64.47,39.434 64.638,39.434 64.758,39.553 64.758,40.297 64.885,40.424 65.012,40.424 65.139,40.297 65.139,38.468 66.072,37.535 66.631,37.535 66.994,37.535
PSRAM_A10: U5.H4 U6.H4 U7.J5 | length 36
  Top Layer w0.102: U5.H4@54.569,36.758 54.573,36.754 54.834,36.754 55.242,36.346 55.459,36.346 55.678,36.127 55.678,35.802 55.903,35.577 56.322,35.577
  Top Layer w0.127: 56.322,35.577 58.223,37.478 58.606,37.478 v7(59.069,37.941)
  layer3 w0.088: 66.994,37.84 67.873,36.961 70.67,36.961 71.166,37.457 71.727,37.457 71.976,37.208 v5(72.117,37.208)
  layer3 w0.102: v7(59.069,37.941) 59.069,38.442 58.445,39.067 58.445,40.595 58.255,40.784 58.255,42.185 58.374,42.304 58.542,42.304 58.662,42.185 58.662,41.211 58.788,41.085 58.967,41.085 59.093,41.211 59.093,42.128 59.294,42.329 59.81,42.329 59.985,42.154 59.985,40.791 60.114,40.662 60.419,40.662 60.547,40.79 60.547,42.317 60.686,42.456 60.998,42.456 61.125,42.329 61.125,40.882 61.252,40.755 61.43,40.755 61.557,40.882 61.557,41.44 61.684,41.567 65.316,41.567 65.443,41.44 65.443,38.595 66.198,37.84 66.994,37.84
PSRAM_A11: U5.H5 U6.H5 U7.H5 | length 36
  Top Layer w0.102: U5.H5@55.319,36.758 55.335,36.742 55.555,36.742 55.889,36.408 56.743,36.408
  Top Layer w0.127: 56.743,36.408 58.078,37.743 58.241,37.743 v7(58.458,37.961)
  layer3 w0.088: 67.005,38.15 67.932,37.222 70.645,37.222 71.112,37.689 71.768,37.689 71.999,37.458 72.242,37.458 72.492,37.208 v5(72.617,37.208)
  layer3 w0.102: v7(58.458,37.961) 58.458,38.519 57.95,39.027 57.95,42.634 58.077,42.761 61.534,42.761 61.636,42.66 61.636,41.999 61.738,41.898 61.941,41.898 62.042,41.999 62.042,42.66 62.144,42.761 62.347,42.761 62.449,42.66 62.449,41.999 62.55,41.898 62.754,41.898 62.855,41.999 62.855,42.66 62.957,42.761 63.16,42.761 63.262,42.66 63.262,41.999 63.363,41.898 63.566,41.898 63.668,41.999 63.668,42.66 63.77,42.761 63.973,42.761 64.074,42.66 64.074,41.999 64.176,41.898 64.379,41.898 64.481,41.999 64.481,42.66 64.582,42.761 64.786,42.761 64.887,42.66 64.887,41.999 64.989,41.898 65.192,41.898 65.294,41.999 65.294,42.66 65.395,42.761 65.647,42.761 65.774,42.634 65.774,38.696 66.32,38.15 67.005,38.15
PSRAM_A12: U5.G3 U6.G3 U7.H9 | length 35.6
  Top Layer w0.102: U5.G3@53.819,37.508 53.796,37.485 53.796,37.286 53.481,36.971 53.481,35.797 54.326,34.952 54.947,34.952 55.27,34.629
  Top Layer w0.127: v7(52.079,33.836) 54.96,33.836 55.27,34.146 55.27,34.629
  layer3 w0.088: 72.364,32.399 72.364,34.814 72.618,35.068 ; 72.618,35.06 72.618,35.068 ; v5(72.618,35.207) 72.618,35.068
  layer3 w0.102: v7(52.079,33.836) 52.079,32.736 55.161,29.654 59.359,29.654 60.697,30.992 63.808,30.992 64.984,29.816 67.331,29.816 67.57,30.055 69.786,30.055 70.02,30.055 71.473,31.508 72.364,32.399
PSRAM_A13: U5.G4 U6.G4 U7.G8 | length 36.9
  Top Layer w0.102: v7(54.155,37.116) 54.185,37.116 54.569,37.5 U5.G4@54.569,37.508
  layer3 w0.088: v5(73.117,35.708) 73.249,35.708 73.502,35.96 74.265,35.96 74.47,36.166 75.229,36.166 75.462,35.933 76.256,35.933 76.82,36.497 78.309,36.497 78.824,35.982 v3(78.824,35.727)
  layer5 w0.127: v6(78.612,35.347) v3(78.824,35.727)
  Bottom Layer w0.127: v7(54.155,37.116) 53.729,36.69 53.729,34.191 54.663,33.257 63.944,33.257 64.325,33.638 75.183,33.638 76.342,34.797 78.062,34.797 v6(78.612,35.347)
PSRAM_A14: U5.F3 U6.F3 U7.G7 | length 33.9
  Top Layer w0.102: U5.F3@53.819,38.258 54.124,38.563 v7(54.173,38.563)
  layer3 w0.088: v3(68.703,40.018) 68.754,40.069 69.431,40.069 71.298,38.202 71.997,38.202 72.37,37.829 72.37,37.823 72.377,37.816 72.371,37.81 72.371,37.605 72.515,37.461 72.72,37.461 72.726,37.467 72.867,37.326 72.867,36.458 v5(73.117,36.208)
  layer5 w0.127: v6(67.127,40.013) 68.698,40.013 v3(68.703,40.018)
  Bottom Layer w0.127: v7(54.173,38.563) 53.504,37.894 52.597,37.894 52.187,38.304 52.187,40.503 51.88,40.81 51.88,43.467 52.826,44.413 61.717,44.413 66.117,40.013 v6(67.127,40.013)
PSRAM_A15: U5.F4 U6.F4 U7.G9 | length 37.7
  Top Layer w0.102: v7(50.926,34.772) 50.926,35.47 51.476,36.02 51.476,36.779 51.873,37.176 53.206,37.176 53.411,37.381 53.411,37.645 53.654,37.888 54.195,37.888 54.565,38.258 U5.F4@54.569,38.258
  layer3 w0.088: v5(73.117,35.208) 73.366,34.959 73.366,34.454 73.131,34.219 73.131,31.229
  layer3 w0.102: v7(50.926,34.772) 51.424,34.274 51.424,32.499 54.862,29.061 61.771,29.061 62.483,28.349 70.84,28.349 71.245,28.754 71.245,29.343 73.131,31.229
PSRAM_A16: U5.E4 U6.E4 U7.J9 | length 37
  Top Layer w0.102: U5.E4@54.569,39.008 54.569,39.006 54.509,38.946 54.64,38.946 54.945,38.64 v7(54.954,38.64)
  layer2 w0.088: v3(71.383,32.903) 71.367,32.919 71.367,34.311 71.513,34.458 71.719,34.458 71.866,34.605 71.866,34.954 71.864,34.956 v5(72.117,35.208)
  layer3 w0.102: v7(54.954,38.64) 54.625,38.64 53.754,39.511 53.2,39.511 52.303,40.408 51.133,40.408 50.755,40.03 50.755,37.213 51.464,36.504 52.039,36.504 52.257,36.286 52.257,35.154 56.272,31.139 59.243,31.139 59.96,31.856 64.722,31.856 66.071,30.507 66.795,30.507 67.675,31.387 69.333,31.387 70.848,32.903 v3(71.383,32.903)
PSRAM_A17: U5.D3 U6.D3 U7.J8 | length 36.2
  Top Layer w0.102: v7(52.713,39.393) 53.449,39.393 53.451,39.391 U5.D3@53.819,39.758
  layer3 w0.088: 71.208,33.698 71.208,34.304 71.367,34.463 71.367,34.812 71.376,34.821 71.376,34.826 71.509,34.958 71.72,34.958 71.866,35.105 71.866,35.35 72.046,35.53 72.046,35.637 v5(72.117,35.708)
  layer3 w0.102: v7(52.713,39.393) 52.452,39.654 52.192,39.654 52.021,39.483 52.021,39.026 51.944,38.949 51.695,38.949 51.604,39.04 51.604,39.482 51.459,39.627 51.294,39.627 51.144,39.477 51.144,37.251 51.534,36.861 51.882,36.861 52.013,36.992 52.013,37.53 52.138,37.655 52.349,37.655 52.525,37.479 52.525,35.344 55.631,32.238 55.965,31.904 56.221,31.904 56.448,32.131 56.692,32.131 56.814,32.009 56.814,31.571 56.937,31.449 57.181,31.449 57.303,31.571 57.303,31.854 57.426,31.977 57.67,31.977 57.792,31.854 57.792,31.59 57.915,31.468 58.159,31.468 58.281,31.59 ; 58.281,31.591 58.404,31.713 59.058,31.713 59.461,32.116 65.36,32.116 66.036,31.44 67.275,31.44 68.086,32.251 69.761,32.251 71.208,33.698
PSRAM_A18: U5.H1 U6.H1 U7.H8 | length 35.9
  Top Layer w0.102: v7(51.579,35.57) 51.758,35.749 51.758,36.601 51.915,36.758 U5.H1@52.319,36.758
  layer3 w0.088: 71.578,32.533 71.87,32.825 71.87,33.326 71.914,33.37 71.914,34.285 71.87,34.329 71.87,34.816 72.014,34.961 72.219,34.961 72.364,35.106 72.364,35.455 v5(72.617,35.708)
  layer3 w0.102: v7(51.579,35.57) 51.579,36.099 51.697,36.217 51.853,36.217 51.972,36.098 51.972,34.962 53.371,33.563 53.371,32.91 53.457,32.824 53.63,32.824 53.772,32.966 53.945,32.966 54.118,32.793 54.118,32.62 53.801,32.303 53.801,32.13 53.974,31.957 54.147,31.957 54.235,32.046 54.463,32.273 54.636,32.273 54.809,32.101 54.809,31.928 54.493,31.611 54.493,31.439 54.666,31.266 54.839,31.266 54.927,31.354 55.155,31.582 55.328,31.582 55.501,31.409 55.501,31.236 55.357,31.092 55.357,30.924 55.64,30.641 59.274,30.641 60.192,31.559 64.453,31.559 65.727,30.285 67.037,30.285 67.872,31.12 68.088,31.12 68.525,30.683 69.007,30.683 69.293,30.969 69.541,30.969 69.687,30.823 69.895,30.823 70.057,30.985 70.057,31.155 69.855,31.357 69.855,31.531 70.031,31.706 70.213,31.706 70.418,31.502 70.555,31.502 70.745,31.692 70.745,31.796 70.554,31.988 70.554,32.23 70.857,32.533 71.578,32.533
PSRAM_A19: U5.G2 U6.G2 U7.D2 | length 36.4
  Top Layer w0.102: v7(51.754,37.876) 52.701,37.876 U5.G2@53.069,37.508
  layer2 w0.088: v4(74.617,38.708) 74.823,38.914 v3(74.823,39.103)
  layer5 w0.127: v6(74.413,39.112) 74.814,39.112 v3(74.823,39.103)
  Bottom Layer w0.127: v7(51.754,37.876) 51.754,37.893 51.091,38.556 51.091,43.568 52.474,44.951 61.899,44.951 66.281,40.569 67.066,40.569 67.447,40.188 67.447,39.78 67.066,39.399 67.066,38.87 67.393,38.543 69.296,38.543 69.606,38.853 74.154,38.853 v6(74.413,39.112)
PSRAM_ADV: U6.J3 U7.D5 | length 37.4
  Top Layer w0.127: U6.J3@53.819,36.008 54.19,35.637 v7(54.198,35.637)
  layer3 w0.088: v5(74.617,37.208) 74.724,37.208 74.943,37.427 75.197,37.427 75.632,37.862 75.857,37.862 v3(76.073,38.078)
  layer5 w0.127: v6(75.748,38.406) 75.748,38.403 v3(76.073,38.078)
  Bottom Layer w0.127: v7(54.198,35.637) 54.559,35.998 54.559,37.308 54.56,39.633 52.651,41.542 52.651,43.436 53.045,43.831 60.774,43.831 64.707,39.898 65.156,39.898 67.065,37.989 69.574,37.989 69.79,38.205 74.157,38.205 74.358,38.406 v6(75.748,38.406)
PSRAM_CE_CS1: JP2.2 R10.2 R17.1 U5.B5 U6.B5 | length 11.7
  Top Layer w0.127: U5.B5@55.319,41.258 55.683,41.622 56.378,41.622 57.409,42.653 R17.1@59.022,42.653 59.022,44.433 58.106,45.349 R10.2@58.106,45.772 ; JP2.2@55.743,48.272 55.743,48.138 55.865,48.26 55.865,48.016 58.087,45.794 R10.2@58.087,45.551
PSRAM_CLK: U6.J2 U7.E8 | length 28.9
  Top Layer w0.102: U6.J2@53.069,36.008 53.069,35.755 v7(54.277,34.547)
  layer3 w0.088: v5(74.117,35.708) 74.265,35.708 74.513,35.956 75.128,35.956 75.429,35.655 76.286,35.655 76.455,35.824 v3(76.758,35.824)
  layer5 w0.127: v6(76.439,35.24) v3(76.758,35.824)
  Bottom Layer w0.127: v7(54.277,34.547) 54.277,34.236 54.656,33.857 55.413,33.857 55.702,34.146 65.961,34.146 66.089,34.018 69.628,34.018 69.903,34.293 75.165,34.293 76.112,35.24 v6(76.439,35.24)
PSRAM_NBL0: U5.A1 U6.A1 U7.A4 | length 32.8
  Top Layer w0.102: U5.A1@52.319,42.008 52.319,42.93 52.665,43.276 v7(53.037,43.276)
  Top Layer w0.127: U7.A4@76.117,37.708 76.71,37.708 v7(76.981,37.98)
  Bottom Layer w0.127: v7(53.037,43.276) 53.489,42.824 53.489,42.34 53.75,42.079 54.477,42.079 54.735,41.821 55.191,41.821 55.728,42.358 56.094,42.358 56.407,42.046 56.733,42.046 56.934,42.246 57.26,42.246 57.46,42.046 57.787,42.046 57.987,42.246 58.314,42.246 58.514,42.046 58.841,42.046 59.411,42.616 60.008,42.616 61.052,41.572 61.052,41.126 60.768,40.842 60.768,40.517 61.052,40.233 61.052,39.787 63.067,37.772 63.806,37.772 64.22,38.186 65.539,38.186 66.679,37.046 74.688,37.046 74.902,37.26 76.262,37.26 v7(76.981,37.98)
PSRAM_NBL1: R9.2 U5.B2 U6.B2 U7.B4 | length 35.5
  Top Layer w0.102: U5.B2@53.069,41.258 53.069,41.535 53.064,41.535 52.677,41.922 52.677,42.671 52.875,42.869 53.296,42.869 53.571,43.144 v7(53.571,43.444)
  Top Layer w0.127: R9.2@51.583,45.553 51.583,45.432 v7(53.571,43.444)
  layer2 w0.088: v4(75.617,37.708) 76.164,37.708 v3(77.124,38.668)
  layer5 w0.127: v6(76.756,38.424) 76.977,38.571 v3(77.124,38.668)
  Bottom Layer w0.127: v7(53.571,43.444) 53.979,43.036 54.432,43.036 54.537,42.931 55.711,42.931 56.047,43.267 60.117,43.267 61.883,41.501 61.883,39.913 63.151,38.645 65.723,38.645 66.941,37.427 74.519,37.427 74.739,37.647 75.979,37.647 v6(76.756,38.424)
PSRAM_NE1: JP2.1 R17.2 U7.F7 | length 37.2
  Top Layer w0.127: JP2.1@58.283,48.272 58.283,48.179 60.422,46.04 R17.2@60.422,42.653 60.599,42.476 60.599,39.518 61.606,38.511 v7(61.606,30.244)
  layer3 w0.088: 72.869,31.442 72.869,35.876 72.954,35.961 73.222,35.961 ; 73.222,35.96 73.47,36.208 v5(73.617,36.208)
  layer3 w0.102: v7(61.606,30.244) 61.64,30.244 62.547,29.337 70.763,29.337 72.869,31.442
PSRAM_OE: U5.A2 U6.A2 U7.C7 | length 36.7
  Top Layer w0.127: U5.A2@53.069,42.008 53.069,42.443 v7(53.09,42.464)
  layer2 w0.088: v4(75.117,36.208) 75.367,35.957 76.263,35.957 76.537,36.231 77.066,36.231 v3(77.225,36.072)
  layer5 w0.127: v6(77.178,36.462) v3(77.225,36.072)
  Bottom Layer w0.127: v7(53.09,42.464) 53.09,41.846 53.698,41.238 54.637,41.238 54.76,41.361 58.211,41.361 58.304,41.268 58.49,41.268 58.587,41.364 58.773,41.364 58.96,41.178 58.96,40.992 58.77,40.802 58.58,40.612 58.58,40.426 58.767,40.24 58.953,40.24 59.143,40.429 59.332,40.619 59.519,40.619 59.705,40.433 59.705,40.246 59.515,40.057 59.326,39.867 59.326,39.681 59.512,39.494 59.698,39.494 59.888,39.684 60.078,39.874 60.264,39.874 60.45,39.687 60.45,39.501 60.261,39.311 60.071,39.122 60.071,38.935 60.257,38.749 60.444,38.749 60.633,38.939 60.823,39.128 61.009,39.128 61.196,38.942 61.196,38.756 61.006,38.566 60.816,38.376 60.816,38.19 61.002,38.004 61.189,38.004 61.378,38.194 61.568,38.383 61.754,38.383 61.941,38.197 61.941,38.011 61.844,37.914 61.844,37.728 62.02,37.551 62.569,37.003 63.909,37.003 64.562,37.656 65.443,37.656 66.434,36.665 74.892,36.665 75.121,36.894 76.721,36.894 77.153,36.462 v6(77.178,36.462)
PSRAM_VDD: R8.2 R9.1 R10.1 R11.1 R13.1 SB4.1 SB5.2 SB38.2 | length 17.9
  Top Layer w0.127: 50.183,46.542 50.185,46.544
  Top Layer w0.3: R9.1@50.183,45.553 50.183,46.542 53.084,46.542 R8.2@53.713,45.913 54.638,46.838 55.524,46.838 56.687,45.675 R10.1@56.687,45.551 ; 50.185,46.544 SB4.1@50.185,47.315
  Top Layer w0.4: 48.45,37.975 48.25,37.975 47.925,38.3 47.925,41 48.3,41.375 48.8,41.375 ; 49.163,42.018 R13.1@49.163,43.763 R11.1@49.163,45.173 49.312,45.322 R9.1@49.952,45.322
